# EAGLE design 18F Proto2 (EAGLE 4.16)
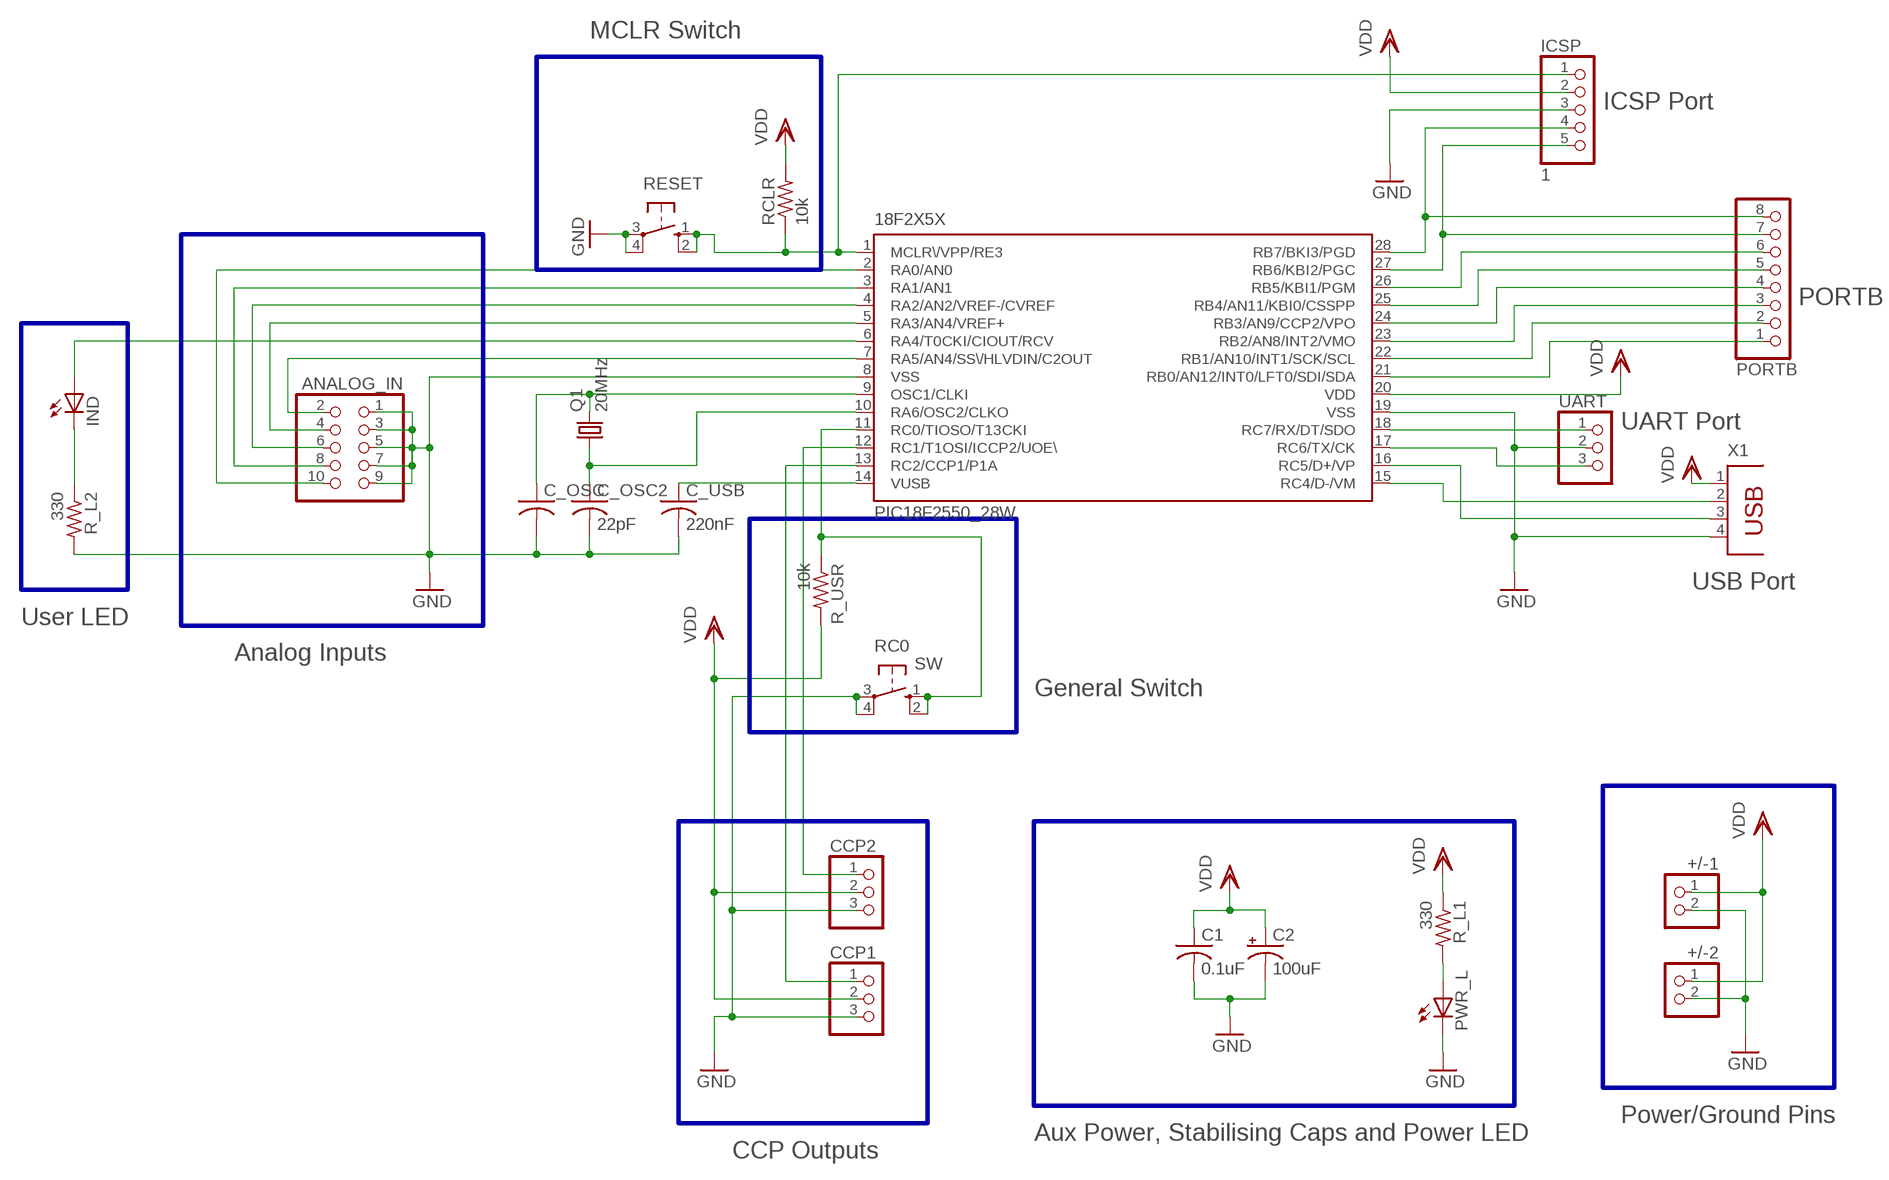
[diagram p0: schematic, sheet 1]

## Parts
18F2X5X  PIC18F2550_28W  [SO28W]
+/-1  PINHD-1X2  [1X02]
+/-2  PINHD-1X2  [1X02]
ANALOG_IN  PINHD-2X5  [2X05]
C1  0.1uF  C-US050-025X075  [C050-025X075]
C2  100uF  CPOL-USE2.5-6  [E2,5-6]
C_OSC  C-US025-025X050  [C025-025X050]
C_OSC2  22pF  C-US025-025X050  [C025-025X050]
C_USB  220nF  C-US050-025X075  [C050-025X075]
CCP1  PINHD-1X3  [1X03]
CCP2  PINHD-1X3  [1X03]
ICSP  1  PINHD-1X5  [1X05]
IND  LED3MM  [LED3MM]
PORTB  PINHD-1X8  [1X08]
PWR_L  LED3MM  [LED3MM]
Q1  20MHz  CRYSTALHC49S  [HC49/S]
R_L1  330  R-US_0204/7  [0204/7]
R_L2  330  R-US_0207/10  [0207/10]
R_USR  10k  R-US_0204/7  [0204/7]
RC0  SW  10-XX  [B3F-10XX]
RCLR  10k  R-US_0204/7  [0204/7]
RESET  10-XX  [B3F-10XX]
UART  PINHD-1X3  [1X03]
X1  PN61729  [PN61729]

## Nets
D+: 18F2X5X.16(RC5/D+/VP) X1.3
D-: 18F2X5X.15(RC4/D-/VM) X1.2
GND: 18F2X5X.8(VSS) 18F2X5X.19(VSS) +/-1.2 +/-2.2 ANALOG_IN.1 ANALOG_IN.3 ANALOG_IN.5 ANALOG_IN.7 ANALOG_IN.9 C1.2 C2.- C_OSC2.2 C_OSC.2 C_USB.2 CCP1.3 CCP2.3 ICSP.3 PWR_L.K(C) R_L2.2 RC0.3(P) RC0.4(P1) RESET.3(P) RESET.4(P1) UART.2 X1.4
MCLR: 18F2X5X.1(MCLR\/VPP/RE3) ICSP.1 RCLR.1 RESET.1(S) RESET.2(S1)
N$4: 18F2X5X.10(RA6/OSC2/CLKO) C_OSC2.1 Q1.1
N$5: PWR_L.A R_L1.2
N$7: 18F2X5X.9(OSC1/CLKI) C_OSC.1 Q1.2
N$9: 18F2X5X.14(VUSB) C_USB.1
N$12: 18F2X5X.2(RA0/AN0) ANALOG_IN.10
N$13: 18F2X5X.3(RA1/AN1) ANALOG_IN.8
N$14: 18F2X5X.4(RA2/AN2/VREF-/CVREF) ANALOG_IN.6
N$15: 18F2X5X.5(RA3/AN4/VREF+) ANALOG_IN.4
N$16: 18F2X5X.6(RA4/T0CKI/CIOUT/RCV) IND.A
N$17: 18F2X5X.7(RA5/AN4/SS\/HLVDIN/C2OUT) ANALOG_IN.2
N$18: IND.K(C) R_L2.1
N$19: 18F2X5X.11(RC0/TIOSO/T13CKI) R_USR.1 RC0.1(S) RC0.2(S1)
N$20: 18F2X5X.12(RC1/T1OSI/ICCP2/UOE\) CCP2.1
N$21: 18F2X5X.13(RC2/CCP1/P1A) CCP1.1
N$22: 18F2X5X.21(RB0/AN12/INT0/LFT0/SDI/SDA) PORTB.1
N$23: 18F2X5X.22(RB1/AN10/INT1/SCK/SCL) PORTB.2
N$24: 18F2X5X.23(RB2/AN8/INT2/VMO) PORTB.3
N$25: 18F2X5X.24(RB3/AN9/CCP2/VPO) PORTB.4
N$26: 18F2X5X.25(RB4/AN11/KBI0/CSSPP) PORTB.5
N$27: 18F2X5X.26(RB5/KBI1/PGM) PORTB.6
PGC: 18F2X5X.27(RB6/KBI2/PGC) ICSP.5 PORTB.7
PGD: 18F2X5X.28(RB7/BKI3/PGD) ICSP.4 PORTB.8
RX: 18F2X5X.18(RC7/RX/DT/SDO) UART.1
TX: 18F2X5X.17(RC6/TX/CK) UART.3
VDD: 18F2X5X.20(VDD) +/-1.1 +/-2.1 C1.1 C2.+ CCP1.2 CCP2.2 ICSP.2 R_L1.1 R_USR.2 RCLR.2 X1.1

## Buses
B$1
B$2
B$3
B$4
B$5
B$6
B$7

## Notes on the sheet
- MCLR Switch
- ICSP Port
- PORTB
- UART Port
- USB Port
- User LED
- Analog Inputs
- General Switch
- Power/Ground Pins
- Aux Power, Stabilising Caps and Power LED
- CCP Outputs

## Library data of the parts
18F2X5X = microchip:PIC18F2*_28: USB Microcontrollers with nanoWatt Technology High-Performance, Enhanced Flash, 28/40/44-Pin, Source: http://ww1.microchip.com/downloads/en/devicedoc/39632c.pdf
+/-1 +/-2 = pinhead:PINHD-1X2: PIN HEADER
ANALOG_IN = pinhead:PINHD-2X5: PIN HEADER
C1 C_OSC C_OSC2 C_USB = rcl:C-US: CAPACITOR, American symbol
C2 = rcl:CPOL-US: POLARIZED CAPACITOR, American symbol
CCP1 CCP2 UART = pinhead:PINHD-1X3: PIN HEADER
ICSP = pinhead:PINHD-1X5: PIN HEADER
IND PWR_L = led:LED: LED
PORTB = pinhead:PINHD-1X8: PIN HEADER
Q1 = crystal:CRYSTAL: CRYSTAL
R_L1 R_L2 R_USR RCLR = rcl:R-US_: RESISTOR, American symbol
RC0 RESET = switch-omron:10-XX: OMRON SWITCH
X1 = con-berg:PN61729: BERG USB connector

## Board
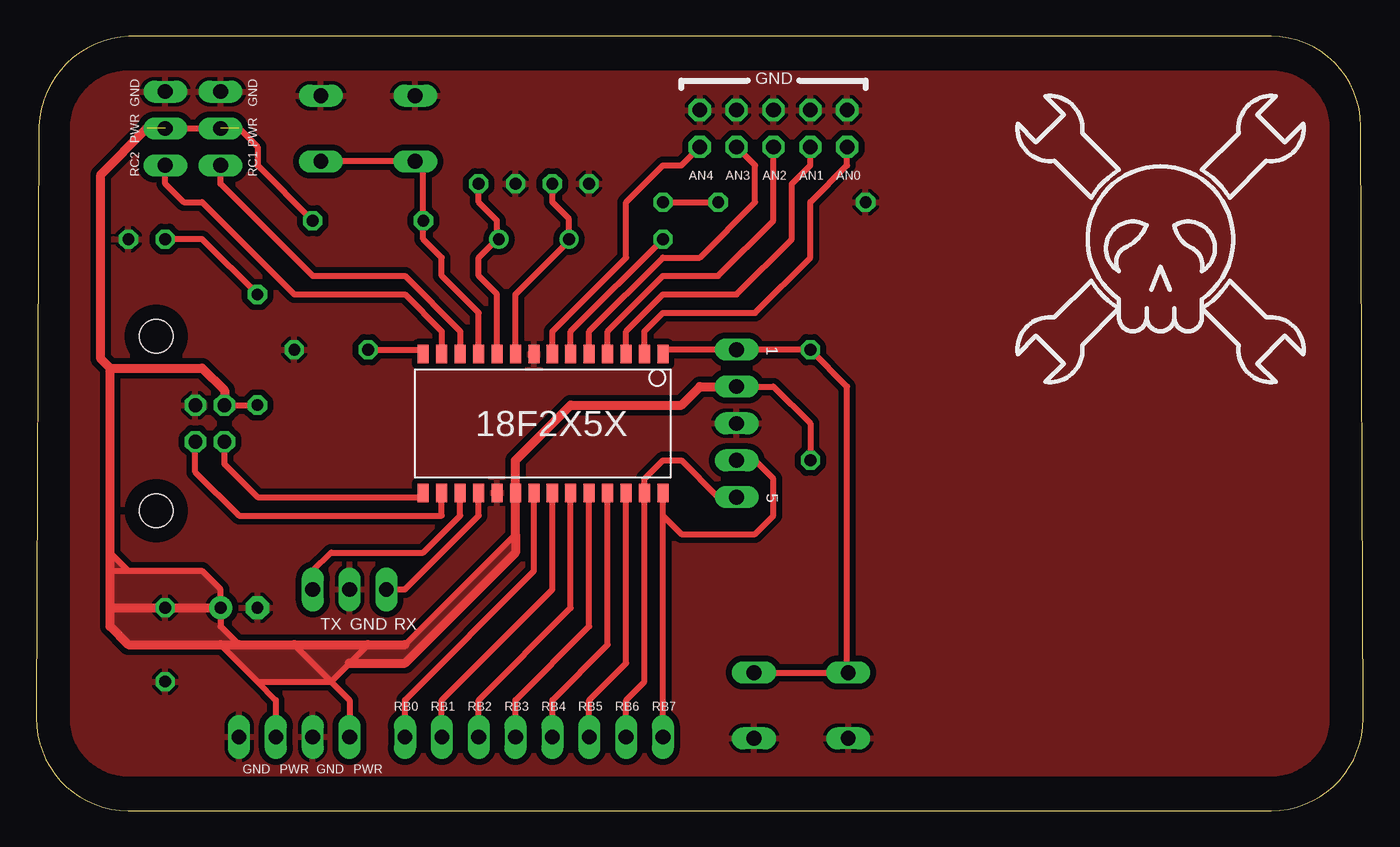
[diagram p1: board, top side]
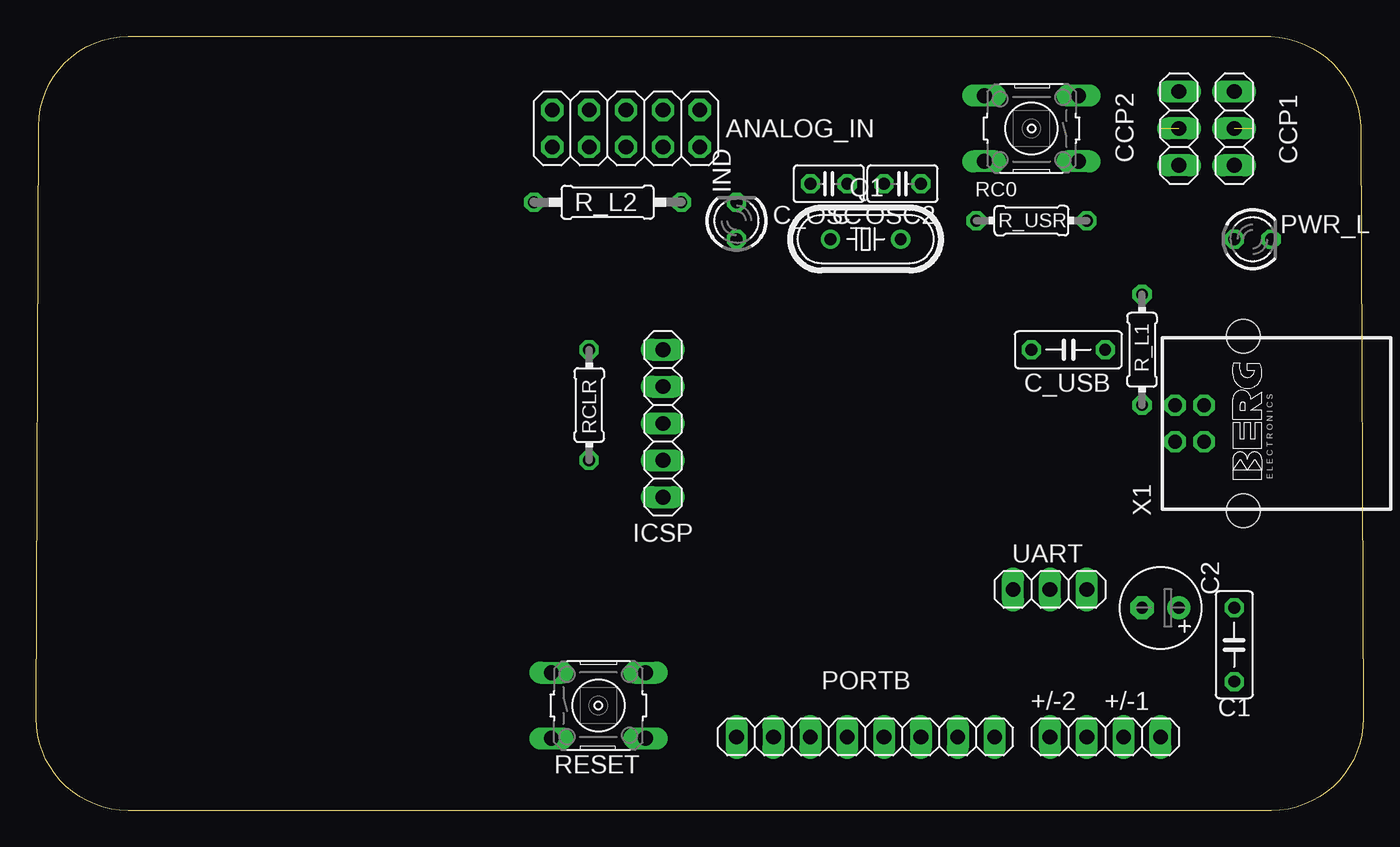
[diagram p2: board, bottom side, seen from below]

Size 91.44 x 53.34 mm. Coordinates in mm from the lower left corner, seen from the top.
Outline: 85.09,0 arc90 91.44,6.34 91.27,47.15 arc90 85.09,53.34 6.98,53.34 arc90 0.17,47.15 0,6.34 arc90 6.35,0 85.09,0
Copper layers (1*16): Top 0.035mm / dielectric 1.5mm / Bottom 0.035mm
Design rules "default": minimum track width 10mil, minimum drill 24mil, track to track 8mil, track to pad 8mil, pad to pad 8mil, via to via 8mil, smd to smd 8mil, copper to edge 40mil, drill to drill 8mil, minimum pad ring 10mil, minimum via ring 8mil, stop-mask expansion 4mil, vias tented up to drill 0mil, thermal gap 10mil

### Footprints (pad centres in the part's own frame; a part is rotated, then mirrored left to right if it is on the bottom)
SO28W = smd 0.762 x 1.27: 1 -7.62,-4.78; 2 -6.35,-4.78; 3 -5.08,-4.78; 4 -3.81,-4.78; 5 -2.54,-4.78; 6 -1.27,-4.78; 7 0,-4.78; 8 1.27,-4.78; 9 2.54,-4.78; 10 3.81,-4.78; 11 5.08,-4.78; 12 6.35,-4.78; 13 7.62,-4.78; 14 8.89,-4.78; 15 8.89,4.78; 16 7.62,4.78; 17 6.35,4.78; 18 5.08,4.78; 19 3.81,4.78; 20 2.54,4.78; 21 1.27,4.78; 22 0,4.78; 23 -1.27,4.78; 24 -2.54,4.78; 25 -3.81,4.78; 26 -5.08,4.78; 27 -6.35,4.78; 28 -7.62,4.78
1X02 = drill 1.016 long: 1 -1.27,0; 2 1.27,0
2X05 = drill 1.016 octagon: 1 -5.08,-1.27; 2 -5.08,1.27; 3 -2.54,-1.27; 4 -2.54,1.27; 5 0,-1.27; 6 0,1.27; 7 2.54,-1.27; 8 2.54,1.27; 9 5.08,-1.27; 10 5.08,1.27
C050-025X075 = drill 0.813 octagon: 1 -2.54,0; 2 2.54,0
E2,5-6 = drill 0.813 pad 1.6 round: + -1.27,0 | drill 0.813 pad 1.6 octagon: - 1.27,0
C025-025X050 = drill 0.813 octagon: 1 -1.27,0; 2 1.27,0
1X03 = drill 1.016 long: 1 -2.54,0; 2 0,0; 3 2.54,0
1X05 = drill 1.016 long: 1 -5.08,0; 2 -2.54,0; 3 0,0; 4 2.54,0; 5 5.08,0
LED3MM = drill 0.813 octagon: A -1.27,0; K 1.27,0
1X08 = drill 1.016 long: 1 -8.89,0; 2 -6.35,0; 3 -3.81,0; 4 -1.27,0; 5 1.27,0; 6 3.81,0; 7 6.35,0; 8 8.89,0
HC49/S = drill 0.813 round: 1 -2.413,0; 2 2.413,0
0204/7 = drill 0.813 octagon: 1 -3.81,0; 2 3.81,0
0207/10 = drill 0.813 octagon: 1 -5.08,0; 2 5.08,0
B3F-10XX = drill 1.016 long: 1 -3.251,2.261; 2 3.251,2.261; 3 -3.251,-2.261; 4 3.251,-2.261
PN61729 = drill 0.95 octagon: 1 1.25,4.71; 2 -1.25,4.71; 3 -1.25,2.71; 4 1.25,2.71 | hole 2.3: -6.02,0; 6.02,0

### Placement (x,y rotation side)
18F2X5X  35.56,26.66 180 top
+/-1  15.24,5.08 0 bottom
+/-2  20.32,5.08 0 bottom
ANALOG_IN  50.8,46.98 180 bottom
C1  8.89,11.43 270 bottom
C2  13.97,13.96 180 bottom
C_OSC  36.83,43.17 180 bottom
C_OSC2  31.75,43.17 180 bottom
C_USB  20.32,31.75 0 bottom
CCP1  8.89,46.98 90 bottom
CCP2  12.7,46.98 90 bottom
ICSP  48.26,26.66 270 bottom
IND  43.18,40.63 90 bottom
PORTB  34.29,5.08 180 bottom
PWR_L  7.62,39.37 0 bottom
Q1  34.29,39.37 180 bottom
R_L1  15.24,31.75 90 bottom
R_L2  52.07,41.91 180 bottom
R_USR  22.86,40.63 0 bottom
RC0  22.86,46.98 180 bottom
RCLR  53.34,27.94 270 bottom
RESET  52.71,7.23 0 bottom
U$1  [HACKADAY_S]  77.47,39.37 0 top
UART  21.59,15.24 0 bottom
X1  8.26,26.66 90 bottom

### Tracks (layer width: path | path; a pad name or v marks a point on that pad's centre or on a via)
D+
  Top 0.406: X1.3 10.96,23.32 13.97,20.32 27.94,20.32 18F2X5X.16
D-
  Top 0.406: X1.2 12.96,23.86 15.24,21.59 26.67,21.59
  Top 0.61: 26.67,21.59 18F2X5X.15
GND
  pour Top (isolate 0.406): 2.54,46.98 arc-90 6.35,50.8 85.09,50.8 arc-90 88.9,46.98 88.9,6.34 arc-90 85.09,2.54 6.35,2.54 arc-90 2.54,6.34
MCLR
  Top 0.406: 55.88,10.16 55.88,29.21 RCLR.1 ICSP.1 43.18,31.75 | RESET.2 55.22,9.5 55.88,10.16 | RESET.1 55.96,10.08 55.88,10.16
  Top 0.61: 43.18,31.75 18F2X5X.1
N$4
  Top 0.406: 18F2X5X.10 31.75,35.55 30.48,36.83 30.48,38.09 31.75,39.37 | 31.75,39.37 Q1.1 | 31.75,39.37 31.75,40.63 30.48,41.91 C_OSC2.1
N$5
  Top 0.406: PWR_L.A 11.43,39.37 R_L1.2
N$7
  Top 0.406: 18F2X5X.9 33.02,35.55 36.7,39.24 | 36.7,39.24 Q1.2 | 36.7,39.24 36.7,40.76 35.56,41.91 C_OSC.1
N$9
  Top 0.406: C_USB.1 26.67,31.75
  Top 0.61: 26.67,31.75 18F2X5X.14
N$12
  Top 0.406: 18F2X5X.2 41.91,33.02 43.18,34.29 49.53,34.29 53.34,38.09 53.34,41.91 55.88,44.45 ANALOG_IN.10
N$13
  Top 0.406: 18F2X5X.3 40.64,33.02 43.18,35.55 48.26,35.55 52.07,39.37 52.07,43.17 53.34,44.45 ANALOG_IN.8
N$14
  Top 0.406: 18F2X5X.4 39.37,33.02 43.18,36.83 46.99,36.83 50.8,40.63 ANALOG_IN.6
N$15
  Top 0.406: 18F2X5X.5 38.1,33.02 43.18,38.09 45.72,38.09 49.53,41.91 49.53,44.45 ANALOG_IN.4
N$16
  Top 0.406: 18F2X5X.6 36.83,33.02 IND.A
N$17
  Top 0.406: 18F2X5X.7 35.56,33.02 40.64,38.09 40.64,41.91 43.18,44.45 44.45,44.45 ANALOG_IN.2
N$18
  Top 0.406: IND.K R_L2.1
N$19
  Top 0.406: 18F2X5X.11 30.48,34.29 27.94,36.83 27.94,38.09 26.67,39.37 R_USR.1 26.67,44.45 26.39,44.72 | 26.39,44.72 RC0.2 | 26.39,44.72 RC0.1
N$20
  Top 0.406: 18F2X5X.12 29.21,33.02 25.4,36.83 19.05,36.83 12.7,43.17 CCP2.1
N$21
  Top 0.406: 18F2X5X.13 27.94,33.02 25.4,35.55 17.78,35.55 11.43,41.91 10.16,41.91 8.89,43.17 CCP1.1
N$22
  Top 0.406: 18F2X5X.21 34.29,16.5 25.4,7.61 PORTB.1
N$23
  Top 0.406: 18F2X5X.22 35.56,15.24 27.94,7.61 PORTB.2
N$24
  Top 0.406: 18F2X5X.23 36.83,13.96 30.48,7.61 PORTB.3
N$25
  Top 0.406: 18F2X5X.24 38.1,12.7 33.02,7.61 PORTB.4
N$26
  Top 0.406: 18F2X5X.25 39.37,11.43 35.56,7.61 PORTB.5
N$27
  Top 0.406: 18F2X5X.26 40.64,10.16 38.1,7.61 PORTB.6
PGC
  Top 0.406: ICSP.5 46.99,21.59 44.45,24.12 43.18,24.12 41.91,22.86 18F2X5X.27 41.91,8.88 40.64,7.61 PORTB.7
PGD
  Top 0.406: 43.18,20.32 18F2X5X.28 | 43.18,20.32 44.45,19.05 49.53,19.05 50.8,20.32 50.8,22.86 49.53,24.12 ICSP.4 | PORTB.8 43.18,20.32
RX
  Top 0.406: 18F2X5X.18 30.48,20.32 25.4,15.24 UART.1
TX
  Top 0.406: 18F2X5X.17 29.21,20.32 26.67,17.78 20.32,17.78 19.05,16.5 UART.3
VDD  (2 unrouted)
  Top 0.406: R_USR.2 15.24,44.45 15.24,45.72 13.97,46.98 7.62,46.98 | X1.1 15.22,27.91 R_L1.1 | RCLR.2 53.34,26.66 50.8,29.21 ICSP.2 | 12.7,11.43 15.24,8.88 | 15.24,8.88 16.51,7.61 +/-1.1 | 20.32,8.88 17.78,11.43 | 20.32,8.88 21.59,7.61 +/-2.1 | 5.08,16.5 6.35,16.5 | 6.35,16.5 11.43,16.5 12.7,15.24 C2.+ 12.7,12.7 13.97,11.43 | 15.24,8.88 20.32,8.88 | 20.32,8.88 21.59,10.16 22.86,11.43 | 5.08,17.78 6.35,16.5 | 25.4,11.43 33.02,19.05
  Top 0.61: 18F2X5X.20 33.02,21.59 | 7.62,46.98 4.45,43.81 4.45,31.11 5.08,30.48 | 5.08,30.48 11.43,30.48 12.96,28.94 X1.1 | 5.08,13.96 C1.1 C2.+ | 18F2X5X.20 33.02,19.05 33.02,17.78 25.4,10.16 21.59,10.16 | 25.4,11.43 22.86,11.43 17.78,11.43 13.97,11.43 12.7,11.43 6.35,11.43 5.08,12.7 5.08,13.96 | 5.08,13.96 5.08,16.5 | 5.08,13.96 5.08,17.78 5.08,30.48 | 18F2X5X.20 33.02,24.12 36.83,27.94 44.45,27.94 45.72,29.21 ICSP.2
  pour Top: 5.08,17.78 5.08,12.7 6.35,11.43 12.7,11.43 15.24,8.88 20.32,8.88 21.59,10.16 25.4,10.16 33.02,17.78 33.02,19.05 25.4,11.43 13.97,11.43 12.7,12.7 12.7,15.24 11.43,16.5 6.35,16.5

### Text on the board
tNames: GND | GND | GND | PWR | PWR | RC2 | RC1 | AN4 | AN3 | AN2 | AN1 | AN0 | 1 | 5 | TX | GND | RX | RB0 | RB1 | RB2 | RB3 | RB4 | RB5 | RB6 | RB7 | GND | PWR | GND | PWR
